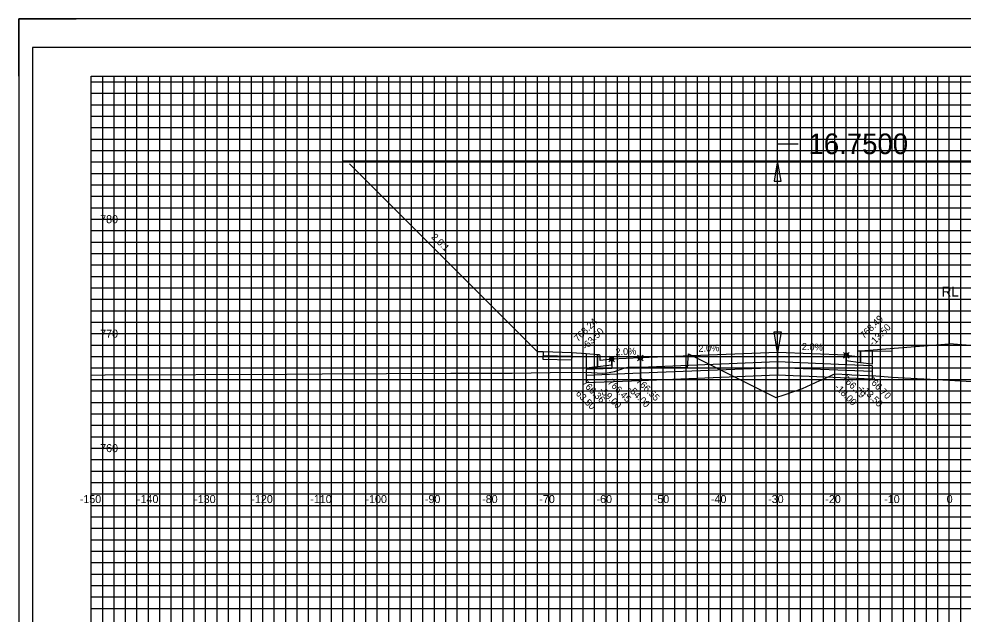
# Model space of a CAD drawing. Extents: x 578243 to 601557, y 174899 to 175559.
# Drawn here: x 599857.2 to 600022.3, y 175014.8 to 175118.8 of the extents above; entities that cross this region are included whole.
import ezdxf

# ---------------------------------------------------------------- set-up
doc = ezdxf.new("R2010")
doc.units = 0
for name, color, linetype in [('E_PROF_Grid', 7, 'Continuous'), ('E_PROF_GridMin', 7, 'Continuous'), ('P_CRDR_Label', 7, 'Continuous'), ('P_CRDR_Link', 7, 'Continuous'), ('P_E_XS_Ground', 7, 'Continuous'), ('P_RW_SlopeIntercepts', 7, 'Continuous'), ('P_XS_Text', 7, 'Continuous'), ('PLT_Sheet_Border', 7, 'Continuous'), ('PLT_Sheet_Info', 7, 'Continuous')]:
    doc.layers.add(name, color=color, linetype=linetype)

msp = doc.modelspace()

# ---------------------------------------------------------------- linework, layer by layer
at = {"layer": 'E_PROF_Grid'}
for p, q in [((599879.84, 174913.8), (599879.84, 175108.8)), ((599889.84, 174913.8), (599889.84, 175108.8)), ((599899.84, 174913.8), (599899.84, 175108.8)), ((599909.84, 174913.8), (599909.84, 175108.8)), ((599919.84, 174913.8), (599919.84, 175108.8)), ((599929.84, 174913.8), (599929.84, 175108.8)), ((599939.84, 174913.8), (599939.84, 175108.8)), ((599949.84, 174913.8), (599949.84, 175108.8)), ((599959.84, 174913.8), (599959.84, 175108.8)), ((599969.84, 174913.8), (599969.84, 175108.8)), ((599979.84, 174913.8), (599979.84, 175108.8)), ((599989.84, 174913.8), (599989.84, 175108.8)), ((599999.84, 174913.8), (599999.84, 175108.8)), ((600009.84, 174913.8), (600009.84, 175108.8)), ((600019.84, 174913.8), (600019.84, 175108.8)), ((599869.84, 175103.8), (600184.84, 175103.8)), ((599869.84, 175093.8), (600184.84, 175093.8)), ((599869.84, 175083.8), (600184.84, 175083.8)), ((599869.84, 175073.8), (600184.84, 175073.8)), ((599869.84, 175063.8), (600184.84, 175063.8)), ((599869.84, 175053.8), (600184.84, 175053.8)), ((599869.84, 175043.8), (600184.84, 175043.8)), ((599869.84, 175033.8), (600184.84, 175033.8)), ((599869.84, 175023.8), (600184.84, 175023.8))]:
    msp.add_line(p, q, dxfattribs=at)
at = {"layer": 'E_PROF_GridMin'}
for p, q in [((599869.84, 175107.8), (600184.84, 175107.8)), ((599871.84, 174913.8), (599871.84, 175108.8)), ((599873.84, 174913.8), (599873.84, 175108.8)), ((599875.84, 174913.8), (599875.84, 175108.8)), ((599877.84, 174913.8), (599877.84, 175108.8)), ((599881.84, 174913.8), (599881.84, 175108.8)), ((599883.84, 174913.8), (599883.84, 175108.8)), ((599885.84, 174913.8), (599885.84, 175108.8)), ((599887.84, 174913.8), (599887.84, 175108.8)), ((599891.84, 174913.8), (599891.84, 175108.8)), ((599893.84, 174913.8), (599893.84, 175108.8)), ((599895.84, 174913.8), (599895.84, 175108.8)), ((599897.84, 174913.8), (599897.84, 175108.8)), ((599901.84, 174913.8), (599901.84, 175108.8)), ((599903.84, 174913.8), (599903.84, 175108.8)), ((599905.84, 174913.8), (599905.84, 175108.8)), ((599907.84, 174913.8), (599907.84, 175108.8)), ((599911.84, 174913.8), (599911.84, 175108.8)), ((599913.84, 174913.8), (599913.84, 175108.8)), ((599915.84, 174913.8), (599915.84, 175108.8)), ((599917.84, 174913.8), (599917.84, 175108.8)), ((599921.84, 174913.8), (599921.84, 175108.8)), ((599923.84, 174913.8), (599923.84, 175108.8)), ((599925.84, 174913.8), (599925.84, 175108.8)), ((599927.84, 174913.8), (599927.84, 175108.8)), ((599931.84, 174913.8), (599931.84, 175108.8)), ((599933.84, 174913.8), (599933.84, 175108.8)), ((599935.84, 174913.8), (599935.84, 175108.8)), ((599937.84, 174913.8), (599937.84, 175108.8)), ((599941.84, 174913.8), (599941.84, 175108.8)), ((599943.84, 174913.8), (599943.84, 175108.8)), ((599945.84, 174913.8), (599945.84, 175108.8)), ((599947.84, 174913.8), (599947.84, 175108.8)), ((599951.84, 174913.8), (599951.84, 175108.8)), ((599953.84, 174913.8), (599953.84, 175108.8)), ((599955.84, 174913.8), (599955.84, 175108.8)), ((599957.84, 174913.8), (599957.84, 175108.8)), ((599961.84, 174913.8), (599961.84, 175108.8)), ((599963.84, 174913.8), (599963.84, 175108.8)), ((599965.84, 174913.8), (599965.84, 175108.8)), ((599967.84, 174913.8), (599967.84, 175108.8)), ((599971.84, 174913.8), (599971.84, 175108.8)), ((599973.84, 174913.8), (599973.84, 175108.8)), ((599975.84, 174913.8), (599975.84, 175108.8)), ((599977.84, 174913.8), (599977.84, 175108.8)), ((599981.84, 174913.8), (599981.84, 175108.8)), ((599983.84, 174913.8), (599983.84, 175108.8)), ((599985.84, 174913.8), (599985.84, 175108.8)), ((599987.84, 174913.8), (599987.84, 175108.8)), ((599991.84, 174913.8), (599991.84, 175108.8)), ((599993.84, 174913.8), (599993.84, 175108.8)), ((599995.84, 174913.8), (599995.84, 175108.8)), ((599997.84, 174913.8), (599997.84, 175108.8)), ((600001.84, 174913.8), (600001.84, 175108.8)), ((600003.84, 174913.8), (600003.84, 175108.8)), ((600005.84, 174913.8), (600005.84, 175108.8)), ((600007.84, 174913.8), (600007.84, 175108.8)), ((600011.84, 174913.8), (600011.84, 175108.8)), ((600013.84, 174913.8), (600013.84, 175108.8)), ((600015.84, 174913.8), (600015.84, 175108.8)), ((600017.84, 174913.8), (600017.84, 175108.8)), ((600021.84, 174913.8), (600021.84, 175108.8)), ((599869.84, 175105.8), (600184.84, 175105.8)), ((599869.84, 175101.8), (600184.84, 175101.8)), ((599869.84, 175099.8), (600184.84, 175099.8)), ((599869.84, 175097.8), (600184.84, 175097.8)), ((599869.84, 175095.8), (600184.84, 175095.8)), ((599869.84, 175091.8), (600184.84, 175091.8)), ((599869.84, 175089.8), (600184.84, 175089.8)), ((599869.84, 175087.8), (600184.84, 175087.8)), ((599869.84, 175085.8), (600184.84, 175085.8)), ((599869.84, 175081.8), (600184.84, 175081.8)), ((599869.84, 175079.8), (600184.84, 175079.8)), ((599869.84, 175077.8), (600184.84, 175077.8)), ((599869.84, 175075.8), (600184.84, 175075.8)), ((599869.84, 175071.8), (600184.84, 175071.8)), ((599869.84, 175069.8), (600184.84, 175069.8)), ((599869.84, 175067.8), (600184.84, 175067.8)), ((599869.84, 175065.8), (600184.84, 175065.8)), ((599869.84, 175061.8), (600184.84, 175061.8)), ((599869.84, 175059.8), (600184.84, 175059.8)), ((599869.84, 175057.8), (600184.84, 175057.8)), ((599869.84, 175055.8), (600184.84, 175055.8)), ((599869.84, 175051.8), (600184.84, 175051.8)), ((599869.84, 175049.8), (600184.84, 175049.8)), ((599869.84, 175047.8), (600184.84, 175047.8)), ((599869.84, 175045.8), (600184.84, 175045.8)), ((599869.84, 175041.8), (600184.84, 175041.8)), ((599869.84, 175039.8), (600184.84, 175039.8)), ((599869.84, 175037.8), (600184.84, 175037.8)), ((599869.84, 175035.8), (600184.84, 175035.8)), ((599869.84, 175031.8), (600184.84, 175031.8)), ((599869.84, 175029.8), (600184.84, 175029.8)), ((599869.84, 175027.8), (600184.84, 175027.8)), ((599869.84, 175025.8), (600184.84, 175025.8)), ((599869.84, 175021.8), (600184.84, 175021.8)), ((599869.84, 175019.8), (600184.84, 175019.8)), ((599869.84, 175017.8), (600184.84, 175017.8)), ((599869.84, 175015.8), (600184.84, 175015.8))]:
    msp.add_line(p, q, dxfattribs=at)
at = {"layer": 'P_CRDR_Label'}
for points in [[(600019.84, 175069.65), (600019.84, 175062.03)], [(599960.35, 175058.86), (599961.34, 175059.85)], [(599960.35, 175059.85), (599961.34, 175058.86)], [(599965.35, 175059.06), (599966.34, 175060.05)], [(599965.35, 175060.05), (599966.34, 175059.06)], [(600001.35, 175059.54), (600002.34, 175060.53)], [(600001.35, 175060.53), (600002.34, 175059.54)]]:
    msp.add_lwpolyline(points, dxfattribs=at)
for centre in [(599960.84, 175059.36), (599965.84, 175059.56), (600001.84, 175060.04)]:
    msp.add_circle(centre, 0.35, dxfattribs=at)
at = {"layer": 'P_CRDR_Link'}
msp.add_line((599914.99, 175093.5), (599947.84, 175060.65), dxfattribs=at)
for points in [[(600004.34, 175060.79), (600019.84, 175062.03)], [(600004.34, 175060.79), (600019.84, 175062.03)], [(600035.34, 175060.79), (600019.84, 175062.03)], [(600035.34, 175060.79), (600019.84, 175062.03)], [(599948.84, 175060.62), (599947.84, 175060.65)], [(599948.84, 175060.62), (599947.84, 175060.65)], [(599953.84, 175060.47), (599948.84, 175060.62)], [(599953.84, 175060.47), (599948.84, 175060.62)], [(599948.84, 175060.62), (599948.85, 175059.95)], [(599953.84, 175059.8), (599948.85, 175059.95)], [(599948.85, 175059.29), (599948.85, 175059.95)], [(599953.84, 175059.8), (599953.83, 175059.14)], [(599956.34, 175060.27), (599953.84, 175060.47)], [(599956.34, 175060.27), (599953.84, 175060.47)], [(599953.84, 175060.47), (599953.84, 175059.8)], [(599958.34, 175060.11), (599956.34, 175060.27)], [(599956.34, 175060.27), (599956.34, 175057.8)], [(599956.34, 175060.27), (599956.34, 175057.8)], [(599956.34, 175060.27), (599956.34, 175057.8)], [(599958.66, 175060.11), (599958.34, 175060.11)], [(599958.66, 175060.11), (599958.34, 175060.11)], [(599958.34, 175060.11), (599958.34, 175058.05)], [(599958.34, 175058.05), (599958.34, 175060.11)], [(599958.74, 175060.07), (599958.66, 175060.11)], [(599958.74, 175060.07), (599958.66, 175060.11)], [(599958.8, 175059.95), (599958.74, 175060.07)], [(599958.8, 175059.95), (599958.74, 175060.07)], [(599958.83, 175059.79), (599958.8, 175059.95)], [(599958.83, 175059.79), (599958.8, 175059.95)], [(599958.84, 175059.11), (599958.83, 175059.79)], [(599958.84, 175059.11), (599958.83, 175059.79)], [(599989.84, 175060.52), (599965.84, 175059.56)], [(600001.84, 175060.04), (599989.84, 175060.52)], [(599989.84, 175060.52), (599989.84, 175058.85)], [(599989.84, 175060.52), (599989.84, 175058.85)], [(600001.84, 175060.04), (600003.84, 175059.79)], [(600001.84, 175060.04), (600003.84, 175059.79)], [(600001.84, 175059.04), (600001.84, 175060.04)], [(600001.84, 175060.04), (600001.84, 175058.37)], [(600003.84, 175059.79), (600003.86, 175060.47)], [(600003.84, 175059.79), (600003.86, 175060.47)], [(600003.86, 175060.47), (600003.88, 175060.63)], [(600003.86, 175060.47), (600003.88, 175060.63)], [(600003.88, 175060.63), (600003.94, 175060.75)], [(600003.88, 175060.63), (600003.94, 175060.75)], [(600003.94, 175060.75), (600004.02, 175060.79)], [(600003.94, 175060.75), (600004.02, 175060.79)], [(600004.02, 175060.79), (600004.34, 175060.79)], [(600004.02, 175060.79), (600004.34, 175060.79)], [(600004.34, 175060.79), (600004.34, 175058.73)], [(600004.34, 175060.79), (600006.34, 175060.77)], [(600004.34, 175058.73), (600004.34, 175060.79)], [(600006.34, 175060.77), (600006.34, 175058.48)], [(600006.34, 175060.77), (600006.34, 175058.48)], [(600006.34, 175060.77), (600006.34, 175058.48)], [(600006.34, 175060.77), (600009.84, 175060.75)], [(600006.34, 175060.77), (600009.84, 175060.75)], [(599953.83, 175059.14), (599948.85, 175059.29)], [(599956.34, 175057.8), (599958.34, 175058.05)], [(599958.34, 175058.05), (599960.84, 175058.36)], [(599958.34, 175058.05), (599960.84, 175058.36)], [(599960.84, 175059.36), (599958.84, 175059.11)], [(599960.84, 175059.36), (599958.84, 175059.11)], [(599965.84, 175059.56), (599960.84, 175059.36)], [(599960.84, 175059.36), (599960.84, 175057.69)], [(599960.84, 175058.36), (599960.84, 175059.36)], [(599965.84, 175059.56), (599965.84, 175057.89)], [(599965.84, 175059.56), (599965.84, 175057.89)], [(599989.84, 175058.85), (599965.84, 175057.89)], [(600001.84, 175058.37), (599989.84, 175058.85)], [(599989.84, 175058.85), (599989.84, 175057.85)], [(599989.84, 175058.85), (599989.84, 175057.85)], [(600004.34, 175058.73), (600001.84, 175059.04)], [(600004.34, 175058.73), (600001.84, 175059.04)], [(600006.34, 175058.19), (600001.84, 175058.37)], [(600006.34, 175058.48), (600004.34, 175058.73)], [(600006.34, 175058.19), (600006.34, 175057.19)], [(599960.84, 175057.69), (599956.34, 175057.51)], [(599956.34, 175057.51), (599956.34, 175056.51)], [(599965.84, 175056.89), (599956.34, 175056.51)], [(599956.34, 175056.51), (599956.34, 175055.18)], [(599965.84, 175057.89), (599960.84, 175057.69)], [(599965.84, 175057.89), (599965.84, 175056.89)], [(599965.84, 175057.89), (599965.84, 175056.89)], [(599989.84, 175057.85), (599965.84, 175056.89)], [(599965.84, 175056.89), (599965.84, 175055.56)], [(599965.84, 175056.89), (599965.84, 175055.56)], [(599989.84, 175056.52), (599965.84, 175055.56)], [(600006.34, 175057.19), (599989.84, 175057.85)], [(599989.84, 175057.85), (599989.84, 175056.52)], [(599989.84, 175057.85), (599989.84, 175056.52)], [(600006.34, 175055.86), (599989.84, 175056.52)], [(600006.34, 175057.19), (600006.34, 175055.86)], [(599965.84, 175055.56), (599956.34, 175055.18)]]:
    msp.add_lwpolyline(points, dxfattribs=at)
at = {"layer": 'P_E_XS_Ground'}
msp.add_lwpolyline([(599869.84, 175056.54), (599872.23, 175056.58), (599872.26, 175056.58), (599872.28, 175056.58), (599904.06, 175056.73), (599910.21, 175056.76), (599910.22, 175056.76), (599932.69, 175056.91), (599943.44, 175056.91), (599950.06, 175057), (599956.32, 175057.07), (599959.29, 175056.92), (599960.02, 175056.96), (599961.3, 175057.2), (599962.97, 175057.77), (599963.66, 175057.92), (599967.8, 175057.92), (599969.03, 175057.88), (599974.11, 175057.91), (599974.11, 175057.91), (599974.24, 175060.26), (599976.57, 175059.1), (599989.5, 175052.63), (599990.98, 175053.13), (599994.2, 175054.2), (599997.23, 175055.61), (599997.24, 175055.61), (599997.43, 175055.7), (599998.07, 175055.98), (599999.55, 175056.67), (599999.84, 175056.8), (600002.35, 175056.66), (600002.84, 175056.63), (600007.02, 175056.41), (600007.84, 175056.35), (600009.82, 175056.2), (600019.84, 175055.67), (600021.82, 175055.53), (600031.84, 175055)], dxfattribs=at)
at = {"layer": 'P_RW_SlopeIntercepts'}
for p, q in [((599989.84, 175096.94), (599993.44, 175096.94)), ((599989.84, 175060.52), (599989.84, 175096.94)), ((599913.84, 175094.02), (600149.84, 175094.02)), ((599989.84, 175094.02), (599989.24, 175090.42)), ((599990.44, 175090.42), (599989.84, 175094.02)), ((599989.24, 175090.42), (599990.44, 175090.42)), ((599989.24, 175064.12), (599990.44, 175064.12)), ((599989.84, 175060.52), (599989.24, 175064.12)), ((599990.44, 175064.12), (599989.84, 175060.52))]:
    msp.add_line(p, q, dxfattribs=at)
at = {"layer": 'PLT_Sheet_Border'}
for points in [[(599857.19, 174898.8), (600197.19, 174898.8), (600197.19, 175118.8), (599857.19, 175118.8)], [(599859.59, 174903.8), (600190.59, 174903.8), (600190.59, 175113.8), (599859.59, 175113.8)]]:
    msp.add_lwpolyline(points, close=True, dxfattribs=at)
at = {"layer": 'PLT_Sheet_Info'}
for p, q in [((599857.19, 175108.8), (599857.19, 175118.8)), ((599857.19, 175118.8), (599867.19, 175118.8)), ((599869.84, 175108.8), (600184.84, 175108.8)), ((599869.84, 174908.8), (599869.84, 175108.8))]:
    msp.add_line(p, q, dxfattribs=at)

# ---------------------------------------------------------------- texts
at = {"layer": 'P_CRDR_Label'}
for s, rotation, p in [('2.0:1', 315.8532, (599929.2, 175080.58)), ('768.24', 45, (599954.93, 175062.31)), ('768.49', 45, (600004.93, 175062.82)), ('-63.50', 45, (599956.34, 175060.9)), ('-13.50', 45, (600006.52, 175061.58)), ('2.0%', 2.2906, (599976, 175060.59)), ('2.0%', 357.7094, (599994.05, 175060.97)), ('2.0%', 2.2906, (599961.5, 175060.01)), ('766.79', 315, (600000.99, 175055.9)), ('766.70', 315, (600005.49, 175055.72)), ('766.36', 315, (599955.49, 175055.04)), ('766.45', 315, (599960.03, 175055.18)), ('766.55', 315, (599965.02, 175055.39)), ('-63.50', 315, (599954.08, 175053.62)), ('-59.00', 315, (599958.58, 175053.8)), ('-54.00', 315, (599963.58, 175054)), ('-18.00', 315, (599999.73, 175054.33)), ('-13.50', 315, (600004.29, 175054.09))]:
    msp.add_text(s, height=1.2, rotation=rotation, dxfattribs=at).set_placement(p)
msp.add_text('RL', height=1.75, dxfattribs=at).set_placement((600018.52, 175070.28))
at = {"layer": 'P_RW_SlopeIntercepts'}
msp.add_text('16.7500', height=3.6, dxfattribs=at).set_placement((599995.24, 175095.17))
at = {"layer": 'P_XS_Text'}
for s, p in [('780', (599871.4, 175083.1)), ('770', (599871.4, 175063.1)), ('760', (599871.4, 175043.1)), ('-150', (599867.84, 175034.2)), ('-140', (599877.84, 175034.2)), ('-130', (599887.84, 175034.2)), ('-120', (599897.84, 175034.2)), ('-110', (599908.13, 175034.2)), ('-100', (599917.79, 175034.2)), ('-90', (599928.17, 175034.2)), ('-80', (599938.18, 175034.2)), ('-70', (599948.18, 175034.2)), ('-60', (599958.18, 175034.2)), ('-50', (599968.18, 175034.2)), ('-40', (599978.18, 175034.2)), ('-30', (599988.18, 175034.2)), ('-20', (599998.18, 175034.2)), ('-10', (600008.47, 175034.2)), ('0', (600019.39, 175034.2)), ('0', (600019.39, 175034.2))]:
    msp.add_text(s, height=1.4, rotation=360, dxfattribs=at).set_placement(p)

doc.saveas('drawing.dxf')
